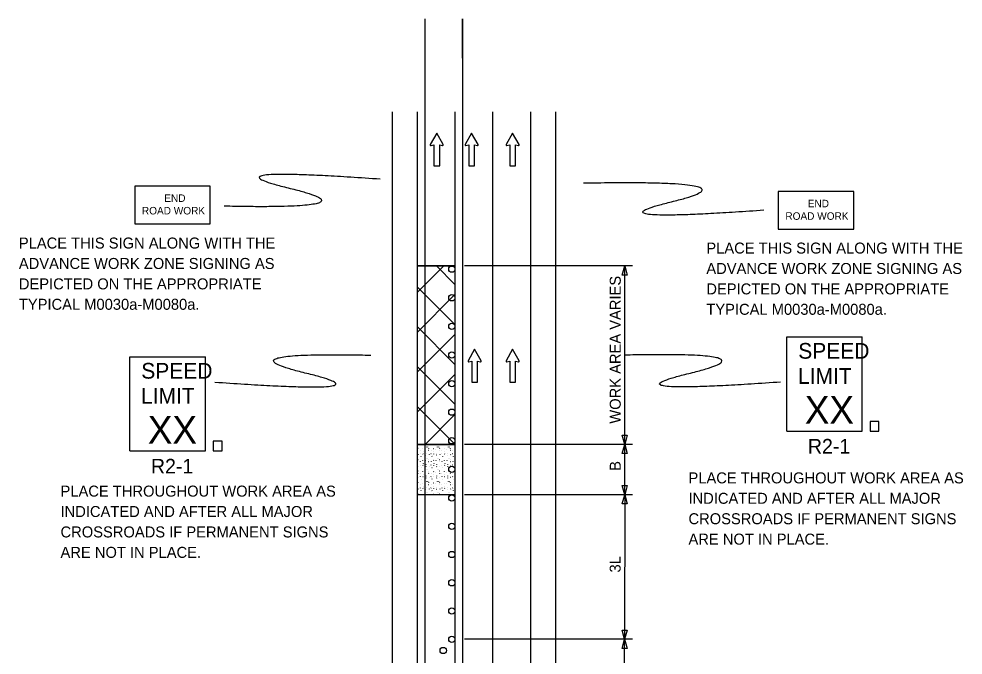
# Model space of a CAD drawing. Extents: x 16735 to 19504, y 6970 to 8243.
# Drawn here: x 16738 to 17339, y 7838 to 8243 of the extents above; entities that cross this region are included whole.
import ezdxf

# ---------------------------------------------------------------- set-up
doc = ezdxf.new("R2010")
doc.units = 0
for name, color, linetype in [('ALI_LEGAL_EX', 7, 'Continuous'), ('MT_SCRATCH_LEVEL_E', 7, 'Continuous'), ('PAVT_EDGE_EX', 7, 'Continuous'), ('TRAFFIC_SIGNS_PR', 7, 'Continuous'), ('TYPICAL_TEXT_DIMEN_PR', 7, 'Continuous')]:
    doc.layers.add(name, color=color, linetype=linetype)

msp = doc.modelspace()

# ---------------------------------------------------------------- linework, layer by layer
at = {"layer": 'ALI_LEGAL_EX'}
for p, q in [((16995.95, 8243.16), (16995.95, 7425.02)), ((17019.95, 8243.16), (17019.95, 7425.02))]:
    msp.add_line(p, q, dxfattribs=at)
for points in [[(17019.95, 8218.16), (17019.95, 8243.16)], [(17015.15, 8183.87), (17015.15, 8158.87)], [(17039.15, 8158.87), (17039.15, 8183.87)], [(17015.15, 8083.87), (17015.15, 8058.87)], [(17039.15, 8058.87), (17039.15, 8083.87)], [(17015.15, 7983.78), (17015.15, 7958.78)], [(17039.15, 7958.87), (17039.15, 7983.87)], [(17015.15, 7883.25), (17015.15, 7858.25)], [(17039.15, 7858.87), (17039.15, 7883.87)]]:
    msp.add_lwpolyline(points, dxfattribs=at)
at = {"layer": 'MT_SCRATCH_LEVEL_E'}
for p, q in [((17003.52, 8170.46), (16999.41, 8163.22)), ((17003.52, 8170.46), (16999.41, 8163.22)), ((17007.67, 8163.22), (17003.52, 8170.46)), ((17007.67, 8163.22), (17003.52, 8170.46)), ((17025.76, 8170.46), (17021.65, 8163.22)), ((17025.76, 8170.46), (17021.65, 8163.22)), ((17029.91, 8163.22), (17025.76, 8170.46)), ((17029.91, 8163.22), (17025.76, 8170.46)), ((17051.87, 8170.46), (17047.76, 8163.22)), ((17051.87, 8170.46), (17047.76, 8163.22)), ((17056.01, 8163.22), (17051.87, 8170.46)), ((17056.01, 8163.22), (17051.87, 8170.46)), ((16999.89, 8162.54), (17001.67, 8162.86)), ((16999.89, 8162.54), (17001.67, 8162.86)), ((17001.67, 8162.86), (17001.67, 8149.6)), ((17001.67, 8162.86), (17001.67, 8149.6)), ((17005.41, 8149.6), (17005.41, 8162.86)), ((17005.41, 8162.86), (17007.19, 8162.54)), ((17005.41, 8149.6), (17005.41, 8162.86)), ((17005.41, 8162.86), (17007.19, 8162.54)), ((17022.13, 8162.54), (17023.91, 8162.86)), ((17022.13, 8162.54), (17023.91, 8162.86)), ((17023.91, 8162.86), (17023.91, 8149.6)), ((17023.91, 8162.86), (17023.91, 8149.6)), ((17027.65, 8149.6), (17027.65, 8162.86)), ((17027.65, 8162.86), (17029.43, 8162.54)), ((17027.65, 8149.6), (17027.65, 8162.86)), ((17027.65, 8162.86), (17029.43, 8162.54)), ((17048.24, 8162.54), (17050.02, 8162.86)), ((17048.24, 8162.54), (17050.02, 8162.86)), ((17050.02, 8162.86), (17050.02, 8149.6)), ((17050.02, 8162.86), (17050.02, 8149.6)), ((17053.76, 8149.6), (17053.76, 8162.86)), ((17053.76, 8162.86), (17055.53, 8162.54)), ((17053.76, 8149.6), (17053.76, 8162.86)), ((17053.76, 8162.86), (17055.53, 8162.54)), ((17001.67, 8149.6), (17005.41, 8149.6)), ((17001.67, 8149.6), (17005.41, 8149.6)), ((17023.91, 8149.6), (17027.65, 8149.6)), ((17023.91, 8149.6), (17027.65, 8149.6)), ((17050.02, 8149.6), (17053.76, 8149.6)), ((17050.02, 8149.6), (17053.76, 8149.6)), ((17027.68, 8032.73), (17023.57, 8025.49)), ((17027.68, 8032.73), (17023.57, 8025.49)), ((17031.83, 8025.49), (17027.68, 8032.73)), ((17031.83, 8025.49), (17027.68, 8032.73)), ((17051.87, 8032.73), (17047.76, 8025.49)), ((17051.87, 8032.73), (17047.76, 8025.49)), ((17056.01, 8025.49), (17051.87, 8032.73)), ((17056.01, 8025.49), (17051.87, 8032.73)), ((17024.05, 8024.81), (17025.83, 8025.12)), ((17024.05, 8024.81), (17025.83, 8025.12)), ((17025.83, 8025.12), (17025.83, 8011.87)), ((17025.83, 8025.12), (17025.83, 8011.87)), ((17029.57, 8011.87), (17029.57, 8025.12)), ((17029.57, 8025.12), (17031.35, 8024.81)), ((17029.57, 8011.87), (17029.57, 8025.12)), ((17029.57, 8025.12), (17031.35, 8024.81)), ((17048.24, 8024.81), (17050.02, 8025.12)), ((17048.24, 8024.81), (17050.02, 8025.12)), ((17050.02, 8025.12), (17050.02, 8011.87)), ((17050.02, 8025.12), (17050.02, 8011.87)), ((17053.76, 8011.87), (17053.76, 8025.12)), ((17053.76, 8025.12), (17055.53, 8024.81)), ((17053.76, 8011.87), (17053.76, 8025.12)), ((17053.76, 8025.12), (17055.53, 8024.81)), ((17025.83, 8011.87), (17029.57, 8011.87)), ((17025.83, 8011.87), (17029.57, 8011.87)), ((17050.02, 8011.87), (17053.76, 8011.87)), ((17050.02, 8011.87), (17053.76, 8011.87))]:
    msp.add_line(p, q, dxfattribs=at)
for centre, start, end in [((16999.82, 8163), 150.42484, 279.96381), ((16999.82, 8163), 150.42484, 279.96381), ((17007.26, 8163), 260.03619, 29.77312), ((17007.26, 8163), 260.03619, 29.77312), ((17022.06, 8163), 150.42484, 279.96381), ((17022.06, 8163), 150.42484, 279.96381), ((17029.5, 8163), 260.03619, 29.77312), ((17029.5, 8163), 260.03619, 29.77312), ((17048.16, 8163), 150.42484, 279.96381), ((17048.16, 8163), 150.42484, 279.96381), ((17055.6, 8163), 260.03619, 29.77312), ((17055.6, 8163), 260.03619, 29.77312), ((17023.98, 8025.27), 150.42484, 279.96381), ((17023.98, 8025.27), 150.42484, 279.96381), ((17031.42, 8025.27), 260.03619, 29.77312), ((17031.42, 8025.27), 260.03619, 29.77312), ((17048.16, 8025.27), 150.42484, 279.96381), ((17048.16, 8025.27), 150.42484, 279.96381), ((17055.6, 8025.27), 260.03619, 29.77312), ((17055.6, 8025.27), 260.03619, 29.77312)]:
    msp.add_arc(centre, 0.463, start, end, dxfattribs=at)
at = {"layer": 'PAVT_EDGE_EX'}
for p, q in [((16975.15, 8183.87), (16975.15, 7354.69)), ((16991.15, 8183.87), (16991.15, 7354.69)), ((17015.15, 8183.87), (17015.15, 7354.69)), ((17039.15, 7358.87), (17039.15, 8183.87)), ((17063.15, 8183.87), (17063.15, 7354.69)), ((17079.15, 8183.87), (17079.15, 7354.69)), ((16991.15, 8085.88), (17015.15, 8085.88)), ((16991.15, 8068.98), (17008.05, 8085.88)), ((17015.24, 8085.88), (16991.24, 8085.88)), ((17015.15, 8074.07), (17003.34, 8085.88)), ((17015.15, 8048.61), (16991.15, 8072.61)), ((16991.15, 8043.53), (17015.15, 8067.53)), ((17015.15, 8023.15), (16991.15, 8047.15)), ((16991.15, 8018.07), (17015.15, 8042.07)), ((17015.15, 7997.7), (16991.15, 8021.7)), ((16991.15, 7992.61), (17015.15, 8016.61)), ((17015.24, 7972.15), (16991.15, 7996.24)), ((16996.15, 7972.15), (17015.15, 7991.16)), ((17015.15, 7972.15), (16991.15, 7972.15)), ((17015.24, 7972.15), (16991.24, 7972.15)), ((16991.24, 7972.15), (17015.24, 7972.15)), ((16993.65, 7971.8), (16993.6, 7971.91)), ((17000.54, 7971.8), (17000.49, 7971.91)), ((17007.43, 7971.8), (17007.37, 7971.91)), ((17014.31, 7971.8), (17014.26, 7971.91)), ((17015.24, 7972.15), (17015.24, 7972.15)), ((16991.55, 7968.33), (16991.5, 7968.26)), ((16991.63, 7969.6), (16991.58, 7969.72)), ((16991.75, 7965.69), (16991.74, 7965.57)), ((16993.03, 7966.26), (16992.98, 7966.19)), ((16993.08, 7968.47), (16993.03, 7968.4)), ((16994.7, 7969.3), (16994.65, 7969.42)), ((16994.83, 7966.01), (16994.78, 7966.13)), ((16994.87, 7967.41), (16994.82, 7967.34)), ((16996.15, 7969.15), (16996.1, 7969.07)), ((16996.8, 7966.54), (16996.75, 7966.66)), ((16997.02, 7970.53), (16996.97, 7970.45)), ((16997.76, 7970.56), (16997.7, 7970.48)), ((16998.44, 7968.33), (16998.39, 7968.26)), ((16998.52, 7969.6), (16998.47, 7969.72)), ((16998.64, 7965.69), (16998.63, 7965.57)), ((16999.92, 7966.26), (16999.87, 7966.19)), ((16999.97, 7968.47), (16999.92, 7968.4)), ((17001.59, 7969.3), (17001.54, 7969.42)), ((17001.72, 7966.01), (17001.67, 7966.13)), ((17001.76, 7967.41), (17001.71, 7967.34)), ((17003.04, 7969.15), (17002.99, 7969.07)), ((17003.69, 7966.54), (17003.63, 7966.66)), ((17003.9, 7970.53), (17003.85, 7970.45)), ((17004.64, 7970.56), (17004.59, 7970.48)), ((17005.33, 7968.33), (17005.28, 7968.26)), ((17005.41, 7969.6), (17005.35, 7969.72)), ((17005.53, 7965.69), (17005.51, 7965.57)), ((17006.81, 7966.26), (17006.76, 7966.19)), ((17006.86, 7968.47), (17006.81, 7968.4)), ((17008.47, 7969.3), (17008.42, 7969.42)), ((17008.6, 7966.01), (17008.55, 7966.13)), ((17008.65, 7967.41), (17008.6, 7967.34)), ((17009.92, 7969.15), (17009.87, 7969.07)), ((17010.57, 7966.54), (17010.52, 7966.66)), ((17010.79, 7970.53), (17010.74, 7970.45)), ((17011.53, 7970.56), (17011.48, 7970.48)), ((17012.21, 7968.33), (17012.16, 7968.26)), ((17012.29, 7969.6), (17012.24, 7969.72)), ((17012.41, 7965.69), (17012.4, 7965.57)), ((17013.69, 7966.26), (17013.64, 7966.19)), ((17013.74, 7968.47), (17013.69, 7968.4)), ((16991.55, 7961.05), (16991.5, 7960.97)), ((16991.63, 7962.31), (16991.58, 7962.43)), ((16993.08, 7961.19), (16993.03, 7961.11)), ((16993.65, 7964.51), (16993.6, 7964.63)), ((16994.7, 7962.02), (16994.65, 7962.13)), ((16994.87, 7960.13), (16994.82, 7960.05)), ((16996.15, 7961.86), (16996.1, 7961.79)), ((16996.61, 7965.34), (16996.56, 7965.27)), ((16996.8, 7959.26), (16996.75, 7959.38)), ((16997.02, 7963.24), (16996.97, 7963.17)), ((16997.76, 7963.27), (16997.7, 7963.2)), ((16998.44, 7961.05), (16998.39, 7960.97)), ((16998.52, 7962.31), (16998.47, 7962.43)), ((16999.97, 7961.19), (16999.92, 7961.11)), ((17000.54, 7964.51), (17000.49, 7964.63)), ((17001.59, 7962.02), (17001.54, 7962.13)), ((17001.76, 7960.13), (17001.71, 7960.05)), ((17003.04, 7961.86), (17002.99, 7961.79)), ((17003.5, 7965.34), (17003.44, 7965.27)), ((17003.69, 7959.26), (17003.63, 7959.38)), ((17003.9, 7963.24), (17003.85, 7963.17)), ((17004.64, 7963.27), (17004.59, 7963.2)), ((17005.33, 7961.05), (17005.28, 7960.97)), ((17005.41, 7962.31), (17005.35, 7962.43)), ((17006.86, 7961.19), (17006.81, 7961.11)), ((17007.43, 7964.51), (17007.37, 7964.63)), ((17008.47, 7962.02), (17008.42, 7962.13)), ((17008.65, 7960.13), (17008.6, 7960.05)), ((17009.92, 7961.86), (17009.87, 7961.79)), ((17010.38, 7965.34), (17010.33, 7965.27)), ((17010.57, 7959.26), (17010.52, 7959.38)), ((17010.79, 7963.24), (17010.74, 7963.17)), ((17011.53, 7963.27), (17011.48, 7963.2)), ((17012.21, 7961.05), (17012.16, 7960.97)), ((17012.29, 7962.31), (17012.24, 7962.43)), ((17013.74, 7961.19), (17013.69, 7961.11)), ((17014.31, 7964.51), (17014.26, 7964.63)), ((16991.55, 7953.76), (16991.5, 7953.69)), ((16991.63, 7955.03), (16991.58, 7955.15)), ((16991.75, 7958.4), (16991.74, 7958.29)), ((16993.03, 7958.98), (16992.98, 7958.9)), ((16993.08, 7953.9), (16993.03, 7953.83)), ((16993.65, 7957.23), (16993.6, 7957.34)), ((16994.7, 7954.73), (16994.65, 7954.85)), ((16994.83, 7958.73), (16994.78, 7958.85)), ((16996.15, 7954.58), (16996.1, 7954.5)), ((16996.61, 7958.06), (16996.56, 7957.98)), ((16997.02, 7955.96), (16996.97, 7955.88)), ((16997.76, 7955.99), (16997.7, 7955.91)), ((16998.44, 7953.76), (16998.39, 7953.69)), ((16998.52, 7955.03), (16998.47, 7955.15)), ((16998.64, 7958.4), (16998.63, 7958.29)), ((16999.92, 7958.98), (16999.87, 7958.9)), ((16999.97, 7953.9), (16999.92, 7953.83)), ((17000.54, 7957.23), (17000.49, 7957.34)), ((17001.59, 7954.73), (17001.54, 7954.85)), ((17001.72, 7958.73), (17001.67, 7958.85)), ((17003.04, 7954.58), (17002.99, 7954.5)), ((17003.5, 7958.06), (17003.44, 7957.98)), ((17003.9, 7955.96), (17003.85, 7955.88)), ((17004.64, 7955.99), (17004.59, 7955.91)), ((17005.33, 7953.76), (17005.28, 7953.69)), ((17005.41, 7955.03), (17005.35, 7955.15)), ((17005.53, 7958.4), (17005.51, 7958.29)), ((17006.81, 7958.98), (17006.76, 7958.9)), ((17006.86, 7953.9), (17006.81, 7953.83)), ((17007.43, 7957.23), (17007.37, 7957.34)), ((17008.47, 7954.73), (17008.42, 7954.85)), ((17008.6, 7958.73), (17008.55, 7958.85)), ((17009.92, 7954.58), (17009.87, 7954.5)), ((17010.38, 7958.06), (17010.33, 7957.98)), ((17010.79, 7955.96), (17010.74, 7955.88)), ((17011.53, 7955.99), (17011.48, 7955.91)), ((17012.21, 7953.76), (17012.16, 7953.69)), ((17012.29, 7955.03), (17012.24, 7955.15)), ((17012.41, 7958.4), (17012.4, 7958.29)), ((17013.69, 7958.98), (17013.64, 7958.9)), ((17013.74, 7953.9), (17013.69, 7953.83)), ((17014.31, 7957.23), (17014.26, 7957.34)), ((16991.63, 7947.74), (16991.58, 7947.86)), ((16991.75, 7951.12), (16991.74, 7951)), ((16993.03, 7951.69), (16992.98, 7951.62)), ((16993.65, 7949.94), (16993.6, 7950.06)), ((16994.7, 7947.45), (16994.65, 7947.56)), ((16994.83, 7951.44), (16994.78, 7951.56)), ((16994.87, 7952.84), (16994.82, 7952.77)), ((16996.61, 7950.78), (16996.56, 7950.7)), ((16996.8, 7951.97), (16996.75, 7952.09)), ((16997.02, 7948.68), (16996.97, 7948.6)), ((16997.76, 7948.7), (16997.7, 7948.63)), ((16998.52, 7947.74), (16998.47, 7947.86)), ((16998.64, 7951.12), (16998.63, 7951)), ((16999.92, 7951.69), (16999.87, 7951.62)), ((17000.54, 7949.94), (17000.49, 7950.06)), ((17001.59, 7947.45), (17001.54, 7947.56)), ((17001.72, 7951.44), (17001.67, 7951.56)), ((17001.76, 7952.84), (17001.71, 7952.77)), ((17003.5, 7950.78), (17003.44, 7950.7)), ((17003.69, 7951.97), (17003.63, 7952.09)), ((17003.9, 7948.68), (17003.85, 7948.6)), ((17004.64, 7948.7), (17004.59, 7948.63)), ((17005.41, 7947.74), (17005.35, 7947.86)), ((17005.53, 7951.12), (17005.51, 7951)), ((17006.81, 7951.69), (17006.76, 7951.62)), ((17007.43, 7949.94), (17007.37, 7950.06)), ((17008.47, 7947.45), (17008.42, 7947.56)), ((17008.6, 7951.44), (17008.55, 7951.56)), ((17008.65, 7952.84), (17008.6, 7952.77)), ((17010.38, 7950.78), (17010.33, 7950.7)), ((17010.57, 7951.97), (17010.52, 7952.09)), ((17010.79, 7948.68), (17010.74, 7948.6)), ((17011.53, 7948.7), (17011.48, 7948.63)), ((17012.29, 7947.74), (17012.24, 7947.86)), ((17012.41, 7951.12), (17012.4, 7951)), ((17013.69, 7951.69), (17013.64, 7951.62)), ((17014.31, 7949.94), (17014.26, 7950.06)), ((16991.55, 7946.48), (16991.5, 7946.4)), ((16991.75, 7943.83), (16991.74, 7943.72)), ((16993.03, 7944.41), (16992.98, 7944.33)), ((16993.08, 7946.62), (16993.03, 7946.54)), ((16993.65, 7942.66), (16993.6, 7942.77)), ((16994.83, 7944.16), (16994.78, 7944.28)), ((16994.87, 7945.56), (16994.82, 7945.48)), ((16996.15, 7947.3), (16996.1, 7947.22)), ((16996.61, 7943.49), (16996.56, 7943.41)), ((16996.8, 7944.69), (16996.75, 7944.81)), ((16997.02, 7941.39), (16996.97, 7941.31)), ((16997.76, 7941.42), (16997.7, 7941.34)), ((16998.44, 7946.48), (16998.39, 7946.4)), ((16998.64, 7943.83), (16998.63, 7943.72)), ((16999.92, 7944.41), (16999.87, 7944.33)), ((16999.97, 7946.62), (16999.92, 7946.54)), ((17000.54, 7942.66), (17000.49, 7942.77)), ((17001.72, 7944.16), (17001.67, 7944.28)), ((17001.76, 7945.56), (17001.71, 7945.48)), ((17003.04, 7947.3), (17002.99, 7947.22)), ((17003.5, 7943.49), (17003.44, 7943.41)), ((17003.69, 7944.69), (17003.63, 7944.81)), ((17003.9, 7941.39), (17003.85, 7941.31)), ((17004.64, 7941.42), (17004.59, 7941.34)), ((17005.33, 7946.48), (17005.28, 7946.4)), ((17005.53, 7943.83), (17005.51, 7943.72)), ((17006.81, 7944.41), (17006.76, 7944.33)), ((17006.86, 7946.62), (17006.81, 7946.54)), ((17007.43, 7942.66), (17007.37, 7942.77)), ((17008.6, 7944.16), (17008.55, 7944.28)), ((17008.65, 7945.56), (17008.6, 7945.48)), ((17009.92, 7947.3), (17009.87, 7947.22)), ((17010.38, 7943.49), (17010.33, 7943.41)), ((17010.57, 7944.69), (17010.52, 7944.81)), ((17010.79, 7941.39), (17010.74, 7941.31)), ((17011.53, 7941.42), (17011.48, 7941.34)), ((17012.21, 7946.48), (17012.16, 7946.4)), ((17012.41, 7943.83), (17012.4, 7943.72)), ((17013.69, 7944.41), (17013.64, 7944.33)), ((17013.74, 7946.62), (17013.69, 7946.54)), ((17014.31, 7942.66), (17014.26, 7942.77)), ((17015.15, 7940.1), (16991.24, 7940.1)), ((17015.24, 7940.1), (16991.24, 7940.1)), ((16991.63, 7940.46), (16991.58, 7940.58)), ((16994.7, 7940.16), (16994.65, 7940.28)), ((16998.52, 7940.46), (16998.47, 7940.58)), ((17001.59, 7940.16), (17001.54, 7940.28)), ((17005.41, 7940.46), (17005.35, 7940.58)), ((17008.47, 7940.16), (17008.42, 7940.28)), ((17012.29, 7940.46), (17012.24, 7940.58))]:
    msp.add_line(p, q, dxfattribs=at)
at = {"layer": 'TRAFFIC_SIGNS_PR'}
for p, q in [((17226.49, 8040.66), (17274.49, 8040.66)), ((17226.49, 7980.66), (17226.49, 8040.66)), ((17274.49, 7980.66), (17274.49, 8040.66)), ((16808.22, 8027.97), (16856.22, 8027.97)), ((16808.22, 7967.97), (16808.22, 8027.97)), ((16856.22, 7967.97), (16856.22, 8027.97)), ((17226.49, 7980.66), (17274.49, 7980.66)), ((16808.22, 7967.97), (16856.22, 7967.97))]:
    msp.add_line(p, q, dxfattribs=at)
for points in [[(16811.33, 8112.69), (16859.33, 8112.69), (16859.33, 8136.69), (16811.33, 8136.69)], [(17220.99, 8109.27), (17268.99, 8109.27), (17268.99, 8133.27), (17220.99, 8133.27)], [(17279.51, 7980.66), (17285.1, 7980.66), (17285.1, 7986.83), (17279.51, 7986.83)], [(16861.24, 7967.97), (16866.83, 7967.97), (16866.83, 7974.14), (16861.24, 7974.14)]]:
    msp.add_lwpolyline(points, close=True, dxfattribs=at)
for centre in [(17013.14, 8083.76), (17013.14, 8065.54), (17013.14, 8047.33), (17013.14, 8029.11), (17013.14, 8010.9), (17013.14, 7992.69), (17013.14, 7974.47), (17013.14, 7956.26), (17013.14, 7938.04), (17013.14, 7920.04), (17013.14, 7902.04), (17013.14, 7884.04), (17013.14, 7866.04), (17013.14, 7848.04), (17013.14, 7848.04), (17013.14, 7848.04), (17013.14, 7848.04), (17007.65, 7840.91)]:
    msp.add_circle(centre, 2, dxfattribs=at)
for points in [[(16967.56, 8141.03), (16852.33, 8149.27), (16966.24, 8121.68), (16868.3, 8123.85)], [(17211.8, 8121.26), (17096.57, 8113.03), (17210.48, 8140.61), (17097.02, 8138.44)], [(16862.29, 8011.84), (16977.52, 8003.6), (16863.61, 8031.19), (16961.55, 8029.02)], [(17222.5, 8011.84), (17107.28, 8003.6), (17221.18, 8031.19), (17123.24, 8029.02)]]:
    msp.add_open_spline(points, degree=2, dxfattribs=at)
at = {"layer": 'TYPICAL_TEXT_DIMEN_PR'}
for p, q in [((17128.24, 8085.88), (17021.23, 8085.88)), ((17121.67, 8080.02), (17123.24, 8085.88)), ((17123.24, 7972.15), (17123.24, 8085.88)), ((17123.24, 8085.88), (17124.81, 8080.02)), ((17123.24, 8080.02), (17121.67, 8080.02)), ((17124.81, 8080.02), (17123.24, 8080.02)), ((17123.24, 7972.15), (17121.67, 7978.02)), ((17121.67, 7978.02), (17123.24, 7978.02)), ((17123.24, 7978.02), (17124.81, 7978.02)), ((17124.81, 7978.02), (17123.24, 7972.15)), ((17128.24, 7972.15), (17021.23, 7972.15)), ((17121.67, 7966.29), (17123.24, 7972.15)), ((17123.24, 7940.1), (17123.24, 7972.15)), ((17123.24, 7972.15), (17124.81, 7966.29)), ((17123.24, 7966.29), (17121.67, 7966.29)), ((17124.81, 7966.29), (17123.24, 7966.29)), ((17123.24, 7940.1), (17121.67, 7945.96)), ((17121.67, 7945.96), (17123.24, 7945.96)), ((17123.24, 7945.96), (17124.81, 7945.96)), ((17124.81, 7945.96), (17123.24, 7940.1)), ((17128.24, 7940.1), (17021.23, 7940.1)), ((17121.67, 7934.23), (17123.24, 7940.1)), ((17123.24, 7940.1), (17123.15, 7848.04)), ((17123.24, 7940.1), (17124.81, 7934.23)), ((17123.24, 7934.23), (17121.67, 7934.23)), ((17124.81, 7934.23), (17123.24, 7934.23)), ((17123.15, 7848.04), (17121.58, 7853.9)), ((17121.58, 7853.9), (17123.15, 7853.9)), ((17123.15, 7853.9), (17124.72, 7853.9)), ((17124.72, 7853.9), (17123.15, 7848.04)), ((17128.15, 7848.04), (17021.23, 7848.04)), ((17121.58, 7842.18), (17123.15, 7848.04)), ((17123.15, 7817.53), (17123.15, 7848.04)), ((17123.15, 7848.04), (17124.72, 7842.18)), ((17123.15, 7842.18), (17121.58, 7842.18)), ((17124.72, 7842.18), (17123.15, 7842.18))]:
    msp.add_line(p, q, dxfattribs=at)

# ---------------------------------------------------------------- texts
at = {"layer": 'TRAFFIC_SIGNS_PR'}
for s, height, p in [('END', 4.789, (16830.08, 8126.6)), ('END', 4.789, (17239.74, 8123.19)), ('ROAD WORK', 4.789, (16815.84, 8118.62)), ('ROAD WORK', 4.789, (17225.5, 8115.2)), ('PLACE THIS SIGN ALONG WITH THE', 7, (16737.49, 8096.9)), ('PLACE THIS SIGN ALONG WITH THE', 7, (17175.19, 8093.7)), ('ADVANCE WORK ZONE SIGNING AS', 7, (16737.49, 8083.9)), ('ADVANCE WORK ZONE SIGNING AS', 7, (17175.19, 8080.7)), ('DEPICTED ON THE APPROPRIATE', 7, (16737.49, 8070.9)), ('DEPICTED ON THE APPROPRIATE', 7, (17175.19, 8067.7)), ('TYPICAL M0030a-M0080a.', 7, (16737.49, 8057.9)), ('TYPICAL M0030a-M0080a.', 7, (17175.19, 8054.7)), ('SPEED', 10, (17233.7, 8026.74)), ('SPEED', 10, (16815.43, 8014.05)), ('LIMIT', 10, (17233.5, 8010.74)), ('LIMIT', 10, (16815.23, 7998.05)), ('XX', 17.538, (17237.88, 7985.36)), ('XX', 17.538, (16819.61, 7972.67)), ('R2-1', 9.3, (17239.84, 7966.36)), ('R2-1', 9.3, (16821.57, 7953.67)), ('PLACE THROUGHOUT WORK AREA AS', 7, (17163.82, 7947.34)), ('PLACE THROUGHOUT WORK AREA AS', 7, (16764.02, 7938.92)), ('INDICATED AND AFTER ALL MAJOR', 7, (17163.82, 7934.34)), ('INDICATED AND AFTER ALL MAJOR', 7, (16764.02, 7925.92)), ('CROSSROADS IF PERMANENT SIGNS', 7, (17163.82, 7921.34)), ('CROSSROADS IF PERMANENT SIGNS', 7, (16764.02, 7912.92)), ('ARE NOT IN PLACE.', 7, (17163.82, 7908.34)), ('ARE NOT IN PLACE.', 7, (16764.02, 7899.92))]:
    msp.add_text(s, height=height, dxfattribs=at).set_placement(p)
at = {"layer": 'TYPICAL_TEXT_DIMEN_PR'}
for s, p in [('WORK AREA VARIES', (17120.68, 7985.37)), ('B', (17120.68, 7955.36)), ('3L', (17120.64, 7890.57))]:
    msp.add_text(s, height=7, rotation=90, dxfattribs=at).set_placement(p)

doc.saveas('drawing.dxf')
